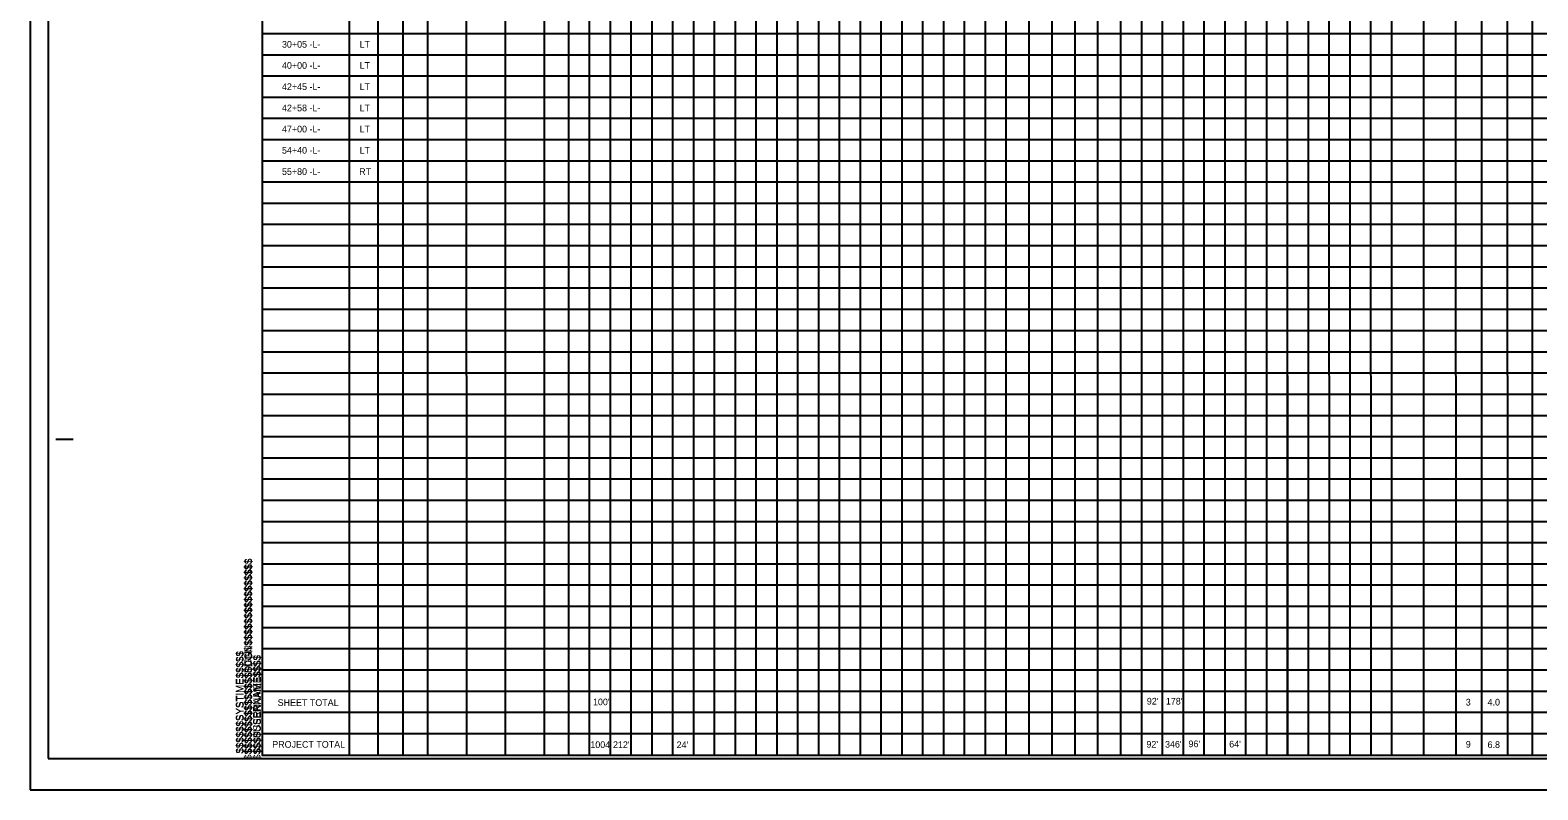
# Model space of a CAD drawing. Extents: x 1912419 to 1914138, y 231793 to 234289.
# Drawn here: x 1912419 to 1913505, y 231793 to 232339 of the extents above; entities that cross this region are included whole.
import ezdxf

# ---------------------------------------------------------------- set-up
doc = ezdxf.new("R2010")
doc.units = 0
for name, color, linetype in [('Sheet Cutting Line CELL', 7, 'Continuous'), ('Sheet Pipe Summary CELL', 7, 'Continuous'), ('Sheet Pipe Summary Grid CELL', 7, 'Continuous'), ('Sheet Plot Border Inside CELL', 7, 'Continuous'), ('Sheet Plot Border Outside CELL', 7, 'Continuous'), ('Sheet Summary Combination CELL', 7, 'Continuous')]:
    doc.layers.add(name, color=color, linetype=linetype)

msp = doc.modelspace()

# ---------------------------------------------------------------- linework, layer by layer
at = {"layer": 'Sheet Cutting Line CELL'}
for p, q in [((1912419.4, 232892.5), (1912419.4, 231792.5)), ((1912419.4, 231792.5), (1914103.4, 231792.5)), ((1912419.4, 231792.5), (1914103.4, 231792.5))]:
    msp.add_line(p, q, dxfattribs=at)
at = {"layer": 'Sheet Pipe Summary CELL'}
for p, q in [((1912437.9, 232045), (1912450.4, 232045)), ((1912437.9, 232045), (1912450.4, 232045)), ((1912586.4, 231817.5), (1912586.4, 231817.5))]:
    msp.add_line(p, q, dxfattribs=at)
msp.add_lwpolyline([(1914086.4, 232867.5), (1912586.4, 232867.5), (1912586.4, 231817.5), (1914086.4, 231817.5)], close=True, dxfattribs=at)
at = {"layer": 'Sheet Pipe Summary Grid CELL'}
for p, q in [((1912649.4, 231817.5), (1912649.4, 232771.3)), ((1912670, 231817.5), (1912669.9, 232771.3)), ((1912705.7, 231817.5), (1912705.7, 232771.3)), ((1912733.7, 231817.5), (1912733.6, 232771.3)), ((1912761.7, 231817.5), (1912761.6, 232771.3)), ((1912789.6, 231817.5), (1912789.6, 232771.3)), ((1912807.1, 231817.5), (1912807.1, 232771.3)), ((1912987.1, 231817.5), (1912987.1, 232771.3)), ((1913092.1, 231817.5), (1913092.1, 232771.3)), ((1913204.7, 231817.6), (1913204.6, 232771.4)), ((1913324.7, 231817.6), (1913324.6, 232771.4)), ((1913339.7, 231817.6), (1913339.6, 232771.4)), ((1913354.7, 231817.6), (1913354.6, 232771.4)), ((1913354.7, 231817.6), (1913354.6, 232771.4)), ((1913369.7, 231817.6), (1913369.6, 232771.4)), ((1913384.7, 231817.6), (1913384.6, 232771.4)), ((1913399.6, 231817.6), (1913399.6, 232771.4)), ((1913445.9, 231817.6), (1913445.8, 232771.4)), ((1913500.9, 231817.6), (1913500.8, 232771.4)), ((1913500.9, 231817.6), (1913500.8, 232771.4)), ((1913464.5, 231817.6), (1913464.4, 232680.7)), ((1912822.1, 231817.5), (1912822.1, 232663.5)), ((1912837.1, 231817.5), (1912837.1, 232663.5)), ((1912852.1, 231817.5), (1912852.1, 232663.5)), ((1912867.1, 231817.5), (1912867.1, 232663.5)), ((1912882.1, 231817.5), (1912882.1, 232663.5)), ((1912897.1, 231817.5), (1912897.1, 232663.5)), ((1912912.1, 231817.5), (1912912.1, 232663.5)), ((1912927.1, 231817.5), (1912927.1, 232663.5)), ((1912942.1, 231817.5), (1912942.1, 232663.5)), ((1912957.1, 231817.5), (1912957.1, 232663.5)), ((1912972.1, 231817.5), (1912972.1, 232663.5)), ((1913002.1, 231817.5), (1913002.1, 232663.5)), ((1913017.1, 231817.5), (1913017.1, 232663.5)), ((1913032.1, 231817.5), (1913032.1, 232663.5)), ((1913047.1, 231817.5), (1913047.1, 232663.5)), ((1913062.1, 231817.5), (1913062.1, 232663.5)), ((1913077.1, 231817.5), (1913077.1, 232663.5)), ((1913092.1, 231817.5), (1913092.1, 232663.5)), ((1913107.1, 231817.5), (1913107.1, 232663.5)), ((1913122.1, 231817.5), (1913122.1, 232663.5)), ((1913138.6, 231817.5), (1913138.6, 232663.5)), ((1913155.1, 231817.5), (1913155.1, 232663.5)), ((1913171.6, 231817.5), (1913171.6, 232663.5)), ((1913188.1, 231817.5), (1913188.1, 232663.5)), ((1913204.6, 231817.5), (1913204.6, 232663.5)), ((1913219.6, 231817.5), (1913219.6, 232663.5)), ((1913234.6, 231817.5), (1913234.6, 232663.5)), ((1913249.6, 231817.5), (1913249.6, 232663.5)), ((1913264.6, 231817.5), (1913264.6, 232663.5)), ((1913279.6, 231817.5), (1913279.6, 232663.5)), ((1913294.6, 231817.5), (1913294.6, 232663.5)), ((1913309.6, 231817.5), (1913309.6, 232663.5)), ((1913324.6, 231817.5), (1913324.6, 232663.5)), ((1913483.1, 231817.6), (1913483, 232657.5)), ((1912687.9, 231817.5), (1912687.8, 232638.1)), ((1912987.1, 231817.5), (1912987.1, 232638.1)), ((1913422.8, 231817.6), (1913422.7, 232638.2)), ((1914086.4, 232336.7), (1912586.4, 232336.7)), ((1914086.4, 232321.4), (1912586.4, 232321.4)), ((1914086.4, 232306.2), (1912586.4, 232306.2)), ((1914086.4, 232290.9), (1912586.4, 232290.9)), ((1914086.4, 232275.6), (1912586.4, 232275.6)), ((1914086.4, 232260.3), (1912586.4, 232260.3)), ((1914086.4, 232245.1), (1912586.4, 232245.1)), ((1914086.4, 232229.8), (1912586.4, 232229.8)), ((1914086.4, 232214.5), (1912586.4, 232214.5)), ((1914086.4, 232199.3), (1912586.4, 232199.3)), ((1914086.4, 232184), (1912586.4, 232184)), ((1914086.4, 232168.7), (1912586.4, 232168.7)), ((1914086.4, 232153.5), (1912586.4, 232153.5)), ((1914086.4, 232138.2), (1912586.4, 232138.2)), ((1914086.4, 232122.9), (1912586.4, 232122.9)), ((1914086.4, 232107.6), (1912586.4, 232107.6)), ((1914086.4, 232092.4), (1912586.4, 232092.4)), ((1914086.4, 232077.1), (1912586.4, 232077.1)), ((1914086.4, 232061.8), (1912586.4, 232061.8)), ((1914086.4, 232046.6), (1912586.4, 232046.6)), ((1914086.4, 232031.3), (1912586.4, 232031.3)), ((1914086.4, 232016), (1912586.4, 232016)), ((1914086.4, 232000.8), (1912586.4, 232000.8)), ((1914086.4, 231985.5), (1912586.4, 231985.5)), ((1914086.4, 231970.2), (1912586.4, 231970.2)), ((1914086.4, 231954.9), (1912586.4, 231954.9)), ((1914086.4, 231939.7), (1912586.4, 231939.7)), ((1914086.4, 231924.4), (1912586.4, 231924.4)), ((1914086.4, 231909.1), (1912586.4, 231909.1)), ((1914086.4, 231893.9), (1912586.4, 231893.9)), ((1914086.4, 231878.6), (1912586.4, 231878.6)), ((1914086.4, 231863.3), (1912586.4, 231863.3)), ((1914086.4, 231848.1), (1912586.4, 231848.1)), ((1914086.4, 231832.8), (1912586.4, 231832.8))]:
    msp.add_line(p, q, dxfattribs=at)
at = {"layer": 'Sheet Plot Border Inside CELL'}
msp.add_lwpolyline([(1912432.4, 231815), (1914098.9, 231815), (1914098.9, 232870.1), (1912432.4, 232870.1)], close=True, dxfattribs=at)
at = {"layer": 'Sheet Plot Border Outside CELL'}
msp.add_lwpolyline([(1912419.4, 231792.5), (1914103.4, 231792.5), (1914103.4, 232892.5), (1912419.4, 232892.5)], close=True, dxfattribs=at)

# ---------------------------------------------------------------- texts
at = {"layer": 'Sheet Pipe Summary CELL'}
for s, p in [('$$$$$$$$$$$$$$$$DGN$$$$$$$$$$$$$$$$', (1912578.8, 231818.4)), ('$$$$$$$$$$$$$$$$DGN$$$$$$$$$$$$$$$$', (1912579.3, 231818.4)), ('$$$$$$SYSTIME$$$$$', (1912572.7, 231818.6)), ('$$$$$$SYSTIME$$$$$', (1912573.2, 231818.6)), ('$$$$USERNAME$$$$', (1912585.1, 231818.5)), ('$$$$USERNAME$$$$', (1912585.6, 231818.5))]:
    msp.add_text(s, height=5.25, rotation=90, dxfattribs=at).set_placement(p)
at = {"layer": 'Sheet Summary Combination CELL'}
for s, p in [('30+05 -L-', (1912600.7, 232326.7)), ('LT', (1912656.6, 232326.7)), ('40+00 -L-', (1912600.7, 232311.5)), ('LT', (1912656.6, 232311.5)), ('42+45 -L-', (1912600.7, 232296.2)), ('LT', (1912656.6, 232296.2)), ('42+58 -L-', (1912600.7, 232280.9)), ('LT', (1912656.6, 232280.9)), ('47+00 -L-', (1912600.7, 232265.7)), ('LT', (1912656.6, 232265.7)), ('54+40 -L-', (1912600.7, 232250.4)), ('LT', (1912656.6, 232250.4)), ('55+80 -L-', (1912600.7, 232235.1)), ('RT', (1912656.3, 232235.1)), ('SHEET TOTAL', (1912597.6, 231852.9)), ("100'", (1912824.6, 231853.4)), ("92'", (1913223.3, 231853.9)), ("178'", (1913237, 231853.9)), ('3', (1913452.9, 231853.2)), ('4.0', (1913468.6, 231853.2)), ('PROJECT TOTAL', (1912593.7, 231822.8)), ("1004'", (1912822.7, 231822.6)), ("212'", (1912839, 231822.6)), ("24'", (1912884.8, 231822.5)), ("92'", (1913223, 231822.9)), ("346'", (1913236.4, 231822.9)), ("96'", (1913253.3, 231823.2)), ("64'", (1913282.6, 231823)), ('9', (1913452.9, 231822.9)), ('6.8', (1913468.6, 231822.6))]:
    msp.add_text(s, height=4.8, dxfattribs=at).set_placement(p)
for s, p in [('$$$$$$$$$$$$$$$$DGN$$$$$$$$$$$$$$$$', (1912578.8, 231814.1)), ('$$$$USERNAME$$$$', (1912585.3, 231814.1))]:
    msp.add_text(s, height=5.25, rotation=90, dxfattribs=at).set_placement(p)

doc.saveas('drawing.dxf')
